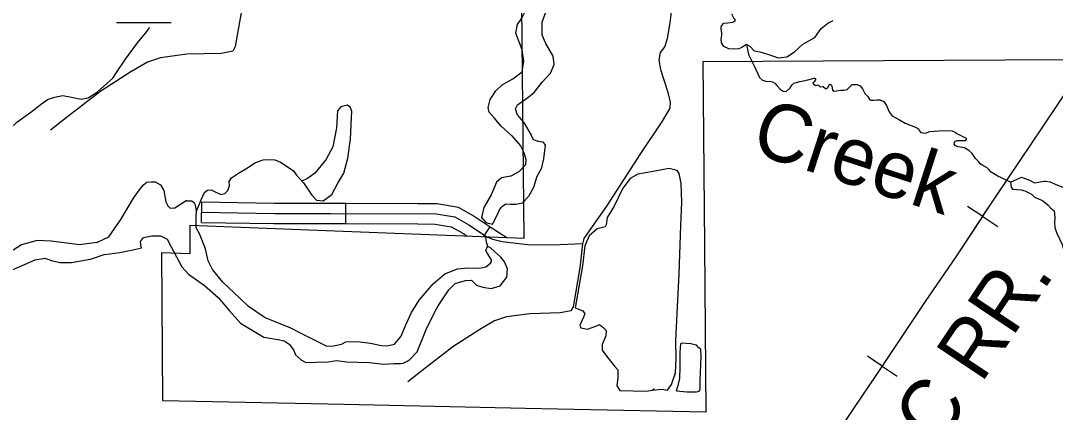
# Model space of a CAD drawing. Extents: x 22866 to 28196, y 1324810 to 1328105.
# Drawn here: x 25465.4 to 25647.4, y 1325934.5 to 1326003.4 of the extents above; entities that cross this region are included whole.
import ezdxf

# ---------------------------------------------------------------- set-up
doc = ezdxf.new("R2010")
doc.units = 0
for name, color, linetype in [('Level 34', 7, 'Continuous'), ('Level 35', 7, 'Continuous'), ('Level 40', 7, 'Continuous'), ('Level 44', 7, 'Continuous'), ('Level 45', 7, 'Continuous'), ('Level 6', 7, 'Continuous')]:
    doc.layers.add(name, color=color, linetype=linetype)

msp = doc.modelspace()

# ---------------------------------------------------------------- linework, layer by layer
at = {"layer": 'Level 34'}
for points in [[(25522.24, 1326039.09), (25522.16, 1326037.93), (25520.61, 1326035.38), (25516.36, 1326029.04), (25509.71, 1326018.67), (25506.39, 1326014.03), (25505.23, 1326012.32), (25505, 1326011.24), (25504.46, 1326006.52), (25503.14, 1325998.86), (25502.68, 1325998.05), (25500.67, 1325997.66), (25494.64, 1325997.51), (25490, 1325996.89), (25487.69, 1325996.12), (25484.77, 1325994.41), (25479.51, 1325991.01), (25473.41, 1325986.29), (25470.63, 1325984.13)], [(25583.69, 1326013.62), (25581.55, 1326010.09), (25580.3, 1326007.04), (25579.89, 1326005.38), (25579.61, 1326003.03), (25579.12, 1326000.26), (25578.71, 1325998.87), (25577.88, 1325997.83), (25577.67, 1325996.45), (25577.95, 1325994.85), (25579.19, 1325990.98), (25579.68, 1325989.06)], [(25579.68, 1325989.06), (25579.61, 1325988.03), (25578.22, 1325985.74), (25574.42, 1325980.06), (25568.47, 1325970.78), (25565.49, 1325966.63), (25564.46, 1325965.1), (25564.25, 1325964.13), (25563.76, 1325959.91), (25562.59, 1325953.05), (25562.17, 1325952.33), (25560.37, 1325951.98), (25554.98, 1325951.84), (25550.83, 1325951.29), (25548.75, 1325950.59), (25546.14, 1325949.07), (25541.44, 1325946.02), (25535.97, 1325941.8), (25533.48, 1325939.86)], [(25564.25, 1325964.13), (25558.96, 1325963.91), (25554.57, 1325963.94), (25550.07, 1325964.5), (25548.48, 1325964.91), (25547.34, 1325965.38)]]:
    msp.add_lwpolyline(points, dxfattribs=at)
at = {"layer": 'Level 35'}
for points in [[(25552.51, 1326001.24), (25552.77, 1326002.74), (25553.55, 1326003.84), (25554.02, 1326004.78), (25554.28, 1326005.82), (25554.28, 1326006.66), (25554.02, 1326007.55), (25553.19, 1326008.34), (25552.35, 1326009.38)], [(25557.11, 1326000.87), (25557.16, 1326003.16), (25557.68, 1326004.62), (25558.36, 1326005.72), (25559.77, 1326007.34), (25560.87, 1326008.44), (25560.87, 1326009.07), (25560.71, 1326009.59), (25559.93, 1326010.17), (25558.57, 1326010.32)], [(25588.74, 1326001.21), (25588.65, 1326002.04), (25588.6, 1326002.2), (25588.7, 1326002.51), (25589.12, 1326002.98), (25589.8, 1326003.04), (25590.64, 1326003.14), (25591.06, 1326003.35), (25591.06, 1326003.61), (25590.85, 1326003.87), (25590.52, 1326004.54)], [(25482.25, 1325994.27), (25483.82, 1325996.65), (25485.94, 1325999.53), (25487.32, 1326001.2), (25488.13, 1326002.22)], [(25596.86, 1325997.54), (25598.64, 1325996.86), (25600.2, 1325997.07), (25601.51, 1325997.91), (25602.97, 1325999.27), (25605.12, 1326000.47), (25606.22, 1326002.04), (25607.42, 1326002.98), (25608.36, 1326003.45)], [(25549.89, 1325984.86), (25548.69, 1325986.33), (25547.8, 1325987.32), (25547.65, 1325988.11), (25547.96, 1325989.57), (25549, 1325991.09), (25550.1, 1325992.14), (25551.98, 1325993.18), (25553.6, 1325994.39), (25553.92, 1325996.27), (25553.6, 1325998.31), (25552.51, 1326001.24)], [(25552.77, 1325986.8), (25552.45, 1325987.9), (25552.82, 1325988.58), (25554.6, 1325989.89), (25555.75, 1325990.78), (25557.16, 1325992.61), (25558.62, 1325994.18), (25559.25, 1325995.69), (25559.04, 1325997.16), (25557.79, 1325999.41), (25557.11, 1326000.87)], [(25593.72, 1325998.85), (25593.09, 1325999.22), (25592.26, 1325998.69), (25591.74, 1325998.48), (25590.9, 1325998.38), (25589.96, 1325998.43), (25589.12, 1325998.85), (25588.7, 1325999.53), (25588.65, 1326000.16), (25588.76, 1326000.84), (25588.74, 1326001.21)], [(25593.09, 1325999.22), (25593.45, 1325997.47), (25594.41, 1325995.48), (25595.38, 1325993.44), (25595.89, 1325992.92)], [(25593.72, 1325998.85), (25594.45, 1325998.12), (25595.45, 1325997.91), (25596.86, 1325997.54)], [(25460.02, 1325981.17), (25462.22, 1325983.23), (25464.68, 1325985.53), (25467.19, 1325987.31), (25469.07, 1325988.78), (25470.12, 1325989.56), (25471.32, 1325989.98), (25472.78, 1325990.24), (25474.3, 1325989.93), (25476.02, 1325989.62), (25477.28, 1325989.82), (25478.9, 1325990.87), (25481.62, 1325993.28), (25482.25, 1325994.27)], [(25595.89, 1325992.92), (25596.49, 1325992.79), (25596.81, 1325992.71), (25597.2, 1325992.74), (25597.67, 1325992.66), (25598.09, 1325992.4), (25598.4, 1325992.01), (25599.03, 1325991.38), (25599.53, 1325990.99), (25600.07, 1325990.96), (25600.78, 1325991.59), (25601.12, 1325992.14), (25601.43, 1325992.4), (25602.53, 1325992.71), (25603.87, 1325993.03), (25604.99, 1325993.29)], [(25606.06, 1325991.8), (25605.75, 1325992.06), (25605.43, 1325991.98), (25605.23, 1325991.96), (25604.89, 1325992.24), (25604.83, 1325992.56), (25605.12, 1325992.79), (25605.28, 1325992.98), (25605.28, 1325993.19), (25604.99, 1325993.29)], [(25606.06, 1325991.8), (25606.56, 1325991.82), (25607.06, 1325991.42), (25607.4, 1325991.63), (25607.71, 1325992.18), (25607.84, 1325992.24), (25607.89, 1325992.21), (25608.08, 1325991.97), (25608.23, 1325991.21), (25608.52, 1325991.01), (25608.94, 1325991.08), (25609.7, 1325991.16), (25610.2, 1325991.21), (25610.8, 1325991.32), (25611.35, 1325991.84), (25611.69, 1325992.16), (25612.16, 1325992.21), (25612.57, 1325992.16), (25613.1, 1325991.97), (25613.49, 1325991.42), (25613.88, 1325990.61), (25614.4, 1325990.12), (25614.77, 1325989.46), (25614.95, 1325989.41), (25615.53, 1325989.41), (25616, 1325989.51), (25616.57, 1325989.49), (25617.23, 1325989.2), (25617.7, 1325988.49), (25618.2, 1325987.37), (25618.74, 1325986.69), (25620.03, 1325985.95), (25620.99, 1325985.35), (25622.8, 1325984.67)], [(25513.92, 1325976.24), (25515.12, 1325974.88), (25516.63, 1325972.68), (25517.42, 1325971.84), (25518.62, 1325971.68), (25520.14, 1325972.84), (25521.18, 1325974.82), (25522.23, 1325976.55), (25522.91, 1325979.22), (25523.43, 1325982.57), (25523.59, 1325986.39), (25523.64, 1325987.44), (25523.38, 1325988.12), (25522.86, 1325988.54), (25521.7, 1325988.28), (25521.13, 1325987.54), (25520.92, 1325984.56), (25520.29, 1325981.21), (25519.04, 1325978.91), (25517.16, 1325976.55), (25515.85, 1325975.61), (25514.85, 1325975.14)], [(25552.77, 1325986.8), (25553.97, 1325985.39), (25555.17, 1325983.24)], [(25549.89, 1325984.86), (25551.78, 1325983.14), (25553.29, 1325981.36), (25553.92, 1325980.21), (25554.28, 1325979), (25554.18, 1325978.06), (25553.03, 1325976.8), (25551.62, 1325976.02), (25549.95, 1325975.76)], [(25622.8, 1325984.67), (25623.37, 1325984.37), (25623.47, 1325984.1), (25623.76, 1325983.71), (25624.57, 1325983.61), (25625.36, 1325983.9), (25626.12, 1325983.97), (25626.93, 1325984.05), (25628, 1325984.1), (25629.28, 1325984.03), (25629.78, 1325983.79), (25630.16, 1325983.51)], [(25555.17, 1325983.24), (25555.54, 1325982.51), (25556.43, 1325982.19), (25557.26, 1325982.09), (25557.68, 1325981.51), (25557.37, 1325979.11), (25556.95, 1325977.33), (25556.22, 1325975.97), (25555.59, 1325974.08), (25554.7, 1325972.46), (25553.6, 1325971.31), (25552.56, 1325971.05), (25551.57, 1325971.05), (25550.73, 1325971.15), (25550, 1325970.58)], [(25639.53, 1325974.97), (25637.93, 1325975.76), (25637.28, 1325976.04), (25636.15, 1325976.78), (25635.74, 1325977.22), (25635.45, 1325977.51), (25634.66, 1325977.95), (25634.22, 1325978.24), (25633.93, 1325978.61), (25633.38, 1325979.16), (25632.78, 1325980.02), (25632.21, 1325980.57), (25631.45, 1325981.02), (25630.3, 1325981.2), (25629.83, 1325981.38), (25629.64, 1325981.7), (25629.67, 1325981.98), (25629.88, 1325982.22), (25630.12, 1325982.32), (25630.85, 1325982.32), (25631.4, 1325982.3), (25631.68, 1325982.32), (25631.81, 1325982.53), (25631.81, 1325982.69), (25630.16, 1325983.51)], [(25496.33, 1325969.89), (25497.4, 1325972.57), (25497.77, 1325973.25), (25498.24, 1325973.57), (25498.92, 1325973.62), (25499.6, 1325973.31), (25500.59, 1325972.84), (25501.27, 1325972.99), (25501.85, 1325973.52), (25502.11, 1325974.41), (25502.05, 1325975.09), (25502.47, 1325975.77), (25503.68, 1325976.6), (25505.3, 1325977.49), (25506.55, 1325978.38), (25508.07, 1325978.91), (25509.11, 1325978.96), (25510.11, 1325978.91), (25511.1, 1325978.54), (25513.3, 1325977.02), (25513.92, 1325976.24)], [(25580.7, 1325943.95), (25580.67, 1325947.2), (25581.22, 1325958.84), (25581.5, 1325967.35), (25581.71, 1325971.48), (25581.57, 1325974.74), (25581.22, 1325976.54), (25580.87, 1325977.02), (25579.49, 1325977.37), (25576.65, 1325976.88), (25573.96, 1325976.4), (25572.64, 1325975.64), (25571.33, 1325973.91), (25569.8, 1325970.79), (25568.56, 1325968.78), (25568.42, 1325967.47), (25568.21, 1325967.12), (25566.83, 1325966.77), (25565.38, 1325965.53), (25564.61, 1325963.79), (25564.2, 1325960.26), (25562.95, 1325952.85), (25563.23, 1325952.74), (25564.27, 1325952.33), (25564.61, 1325951.84), (25564.41, 1325951.22), (25563.78, 1325949.83), (25563.92, 1325949.35), (25565.1, 1325949.14), (25566.55, 1325949.63), (25567.24, 1325949.97), (25567.8, 1325949.49), (25568.42, 1325948.86), (25568.35, 1325947.96), (25567.66, 1325946.44), (25567.66, 1325945.4), (25568.49, 1325944.29), (25569.87, 1325942.63), (25570.43, 1325941.94), (25570.43, 1325940.62), (25570.29, 1325939.17), (25570.77, 1325938.34), (25570.84, 1325938.33)], [(25478.78, 1325964.39), (25480.86, 1325965.39), (25483, 1325968.43), (25485.2, 1325972.19), (25486.29, 1325973.66), (25486.97, 1325974.55), (25487.6, 1325975.02), (25488.38, 1325975.07), (25489.06, 1325975.07), (25490, 1325974.5), (25490.58, 1325973.5), (25490.89, 1325971.51), (25491.26, 1325970.83), (25491.68, 1325970.42), (25492.51, 1325970.47), (25494.5, 1325971.78)], [(25549.95, 1325975.76), (25549.11, 1325975.02), (25548.17, 1325972.77), (25546.89, 1325970.54)], [(25639.53, 1325974.97), (25641.49, 1325975.9)], [(25639.53, 1325974.97), (25639.63, 1325974.12), (25639.89, 1325973.75), (25640.62, 1325973.73), (25641.41, 1325973.65), (25642.06, 1325973.46), (25643.21, 1325972.86), (25643.76, 1325972.34), (25645.15, 1325971.79), (25646.09, 1325971.03), (25646.64, 1325970.43), (25647.21, 1325969.93), (25647.29, 1325969.43), (25647.32, 1325968.65), (25647.29, 1325967.97), (25647.32, 1325967.03), (25647.63, 1325966.11), (25648.15, 1325965.04), (25648.6, 1325964.04), (25648.86, 1325963.22), (25649.2, 1325962.13)], [(25641.49, 1325975.9), (25642.87, 1325975.32), (25643.76, 1325974.88), (25645.43, 1325975.14), (25645.72, 1325975.16), (25646.51, 1325975.06), (25647.53, 1325974.56), (25648.73, 1325974.09), (25650.06, 1325973.46), (25651.68, 1325972.71), (25652.49, 1325972.08), (25654.14, 1325970.95)], [(25496.33, 1325969.89), (25496.15, 1325970.95), (25495.94, 1325971.32), (25495.52, 1325971.63), (25494.68, 1325971.63), (25494.5, 1325971.78)], [(25508.2, 1325951.21), (25505.48, 1325953.1), (25504.01, 1325954.51), (25500.93, 1325957.39), (25499.15, 1325959.64), (25498.37, 1325961.15), (25497.9, 1325963.25), (25496.91, 1325965.76), (25496.28, 1325966.96), (25496.23, 1325968.11), (25496.23, 1325969.11), (25496.33, 1325969.89)], [(25546.89, 1325970.54), (25546.43, 1325968.78), (25547.23, 1325967.88)], [(25547.23, 1325967.88), (25548.42, 1325967.63), (25549.28, 1325969.3)], [(25549.28, 1325969.3), (25549.58, 1325969.99), (25550, 1325970.58)], [(25547.21, 1325967.9), (25547.15, 1325967.73)], [(25480.16, 1325962.25), (25482.84, 1325962.62), (25485.09, 1325963.09), (25486.19, 1325963.3), (25486.61, 1325963.46), (25486.5, 1325963.98), (25486.45, 1325964.56), (25486.97, 1325965.24), (25488.44, 1325965.55), (25490, 1325965.55), (25491.15, 1325964.97), (25491.83, 1325963.61), (25493.72, 1325960.11), (25494.92, 1325958.8), (25497.74, 1325956.81), (25500.15, 1325954.72), (25502.13, 1325952.36), (25504.07, 1325950.17), (25508.14, 1325947.71)], [(25478.78, 1325964.39), (25475.72, 1325963.98), (25470.75, 1325964.6), (25468.3, 1325964.71), (25465.52, 1325963.98), (25461.71, 1325961.57), (25458.62, 1325958.64), (25455.85, 1325955.34), (25452.82, 1325952.46), (25450.36, 1325950.89), (25447.28, 1325949.27), (25442.83, 1325947.02), (25441.31, 1325946.81), (25440.63, 1325946.91), (25440.43, 1325947.91), (25440.63, 1325949.53)], [(25547.19, 1325965.38), (25547.27, 1325964.49), (25547.51, 1325963.68)], [(25480.16, 1325962.25), (25477.6, 1325961.4), (25474.31, 1325960.77), (25472.27, 1325960.77), (25471.02, 1325961.09), (25469.71, 1325961.56), (25467.88, 1325961.24), (25463.69, 1325959.46), (25461.18, 1325957.21), (25460.4, 1325956.17), (25459.98, 1325955.54), (25458.36, 1325954.18), (25456.32, 1325951.87), (25454.02, 1325949.78), (25451.09, 1325947.37), (25447.17, 1325945.59), (25443.72, 1325944.76), (25441.31, 1325943.92), (25439.22, 1325942.61), (25435.72, 1325940.99), (25432.69, 1325938.69), (25430.19, 1325936.53)], [(25538.85, 1325953.22), (25540.69, 1325956.04), (25541.84, 1325957.14), (25543.62, 1325957.71), (25544.67, 1325957.76), (25545.55, 1325956.87), (25546.7, 1325956.51), (25548.17, 1325956.25), (25549.74, 1325956.77), (25550.94, 1325958.29), (25551.04, 1325959.75), (25550.52, 1325960.96), (25549.84, 1325961.79), (25548.8, 1325962.73), (25547.96, 1325963.52)], [(25548.22, 1325961.32), (25547.49, 1325962.42), (25547.23, 1325962.94), (25547.51, 1325963.68)], [(25547.96, 1325963.52), (25547.51, 1325963.68)], [(25535.48, 1325954.25), (25537.97, 1325957.08), (25540.01, 1325958.86), (25542.26, 1325959.75), (25544.04, 1325959.91), (25546.18, 1325959.86), (25547.23, 1325960.12), (25548.06, 1325960.75), (25548.22, 1325961.06), (25548.22, 1325961.32)], [(25534.17, 1325952.06), (25535.48, 1325954.25)], [(25536.73, 1325949.08), (25538.39, 1325952.43), (25538.85, 1325953.22)], [(25508.2, 1325951.21), (25512.85, 1325949.38), (25514.89, 1325948.28), (25517.71, 1325946.92)], [(25517.71, 1325946.92), (25519.22, 1325946.15), (25520.42, 1325946.2), (25521.83, 1325946.51), (25522.56, 1325946.88), (25524.65, 1325946.98), (25526.95, 1325946.67), (25528.78, 1325946.25), (25529.78, 1325946.2), (25531.14, 1325946.51), (25532.34, 1325947.87), (25533.17, 1325949.86), (25534.17, 1325952.06)], [(25508.14, 1325947.71), (25510.64, 1325947.3), (25511.74, 1325947.09), (25512.63, 1325946.51), (25513.36, 1325945.47), (25513.73, 1325944.58), (25514.77, 1325943.64), (25515.56, 1325943.27), (25517.44, 1325943.32)], [(25517.44, 1325943.32), (25519.48, 1325943.37), (25520.94, 1325943.58), (25522.77, 1325943.37), (25524.65, 1325943.32), (25526.74, 1325943.27), (25529.2, 1325942.96), (25531.08, 1325943.06), (25532.23, 1325943.06), (25532.7, 1325943.11), (25533.75, 1325943.69), (25535.11, 1325945.15), (25536.73, 1325949.08)], [(25580.75, 1325938.25), (25582.59, 1325938.11), (25583.8, 1325938.08), (25584.28, 1325938.08), (25584.73, 1325938.22), (25584.91, 1325938.6), (25584.94, 1325940.09), (25585.11, 1325944.34), (25585.04, 1325945.63), (25584.7, 1325945.83), (25584.28, 1325946.32), (25583.31, 1325946.56), (25581.72, 1325946.66), (25581.45, 1325946.53), (25581.38, 1325945.04), (25581.38, 1325942.44), (25581.31, 1325940.43), (25581.03, 1325939.22), (25580.72, 1325938.22)], [(25576.85, 1325938.61), (25576.52, 1325938.41), (25578.18, 1325938.54), (25579.21, 1325938.41), (25579.91, 1325939.38), (25580.6, 1325941.45), (25580.7, 1325943.95)], [(25570.84, 1325938.33), (25575.41, 1325938.2), (25576.52, 1325938.41)]]:
    msp.add_lwpolyline(points, dxfattribs=at)
at = {"layer": 'Level 40'}
for p, q in [((25634.64, 1325968.94), (25631.99, 1325970.69)), ((25634.64, 1325968.94), (25637.28, 1325967.19)), ((25616.98, 1325942.63), (25614.35, 1325944.39)), ((25616.98, 1325942.63), (25619.61, 1325940.87))]:
    msp.add_line(p, q, dxfattribs=at)
for points in [[(25634.63, 1325968.94), (25639.05, 1325975.56), (25645.24, 1325984.75), (25653.04, 1325996.34)], [(25634.63, 1325968.94), (25639.05, 1325975.56), (25645.24, 1325984.75), (25653.04, 1325996.34)], [(25492.71, 1325755.52), (25496.31, 1325761.34), (25500.34, 1325767.54), (25504.76, 1325774.59), (25516.78, 1325792.11), (25526.44, 1325807.02), (25536.83, 1325822.38), (25545.04, 1325834.64), (25558.16, 1325854.38), (25568.88, 1325870.46), (25579.1, 1325885.61), (25587.97, 1325899.18), (25600.25, 1325917.68), (25612.11, 1325935.34), (25615.88, 1325940.99), (25624.6, 1325954.01), (25629.96, 1325961.87), (25634.64, 1325968.94)]]:
    msp.add_lwpolyline(points, dxfattribs=at)
at = {"layer": 'Level 44'}
msp.add_line((25482.24, 1326003.07), (25491.84, 1326003.07), dxfattribs=at)
at = {"layer": 'Level 45'}
for p, q in [((25497.22, 1325967.91), (25497.28, 1325971.51)), ((25522.59, 1325967.69), (25522.6, 1325971.29)), ((25546.81, 1325965.4), (25547.98, 1325967.16))]:
    msp.add_line(p, q, dxfattribs=at)
for points in [[(25624.6, 1325954.01), (25629.96, 1325961.87), (25635.14, 1325969.7), (25639.05, 1325975.56), (25645.24, 1325984.75), (25656.03, 1326000.79), (25663.49, 1326012.3), (25670.2, 1326022.41), (25674.43, 1326028.62)], [(25497.28, 1325971.51), (25509.95, 1325971.3)], [(25509.95, 1325971.3), (25510.06, 1325971.3), (25519.95, 1325971.3), (25522.6, 1325971.29)], [(25522.6, 1325971.29), (25535.27, 1325971.24)], [(25535.27, 1325971.24), (25538.64, 1325971.23), (25542.34, 1325970.6), (25545.16, 1325969.03), (25547.98, 1325967.16)], [(25497.25, 1325969.71), (25510.05, 1325969.5), (25519.94, 1325969.5), (25538.49, 1325969.43), (25541.74, 1325968.88), (25544.23, 1325967.49), (25547.54, 1325965.29)], [(25497.22, 1325967.91), (25509.89, 1325967.7)], [(25509.89, 1325967.7), (25510.03, 1325967.7), (25519.94, 1325967.7), (25522.59, 1325967.69)], [(25522.59, 1325967.69), (25535.26, 1325967.64)], [(25535.26, 1325967.64), (25538.33, 1325967.63), (25541.13, 1325967.15), (25543.29, 1325965.95), (25543.96, 1325965.51)], [(25547.98, 1325967.16), (25550.89, 1325965.24)], [(25587.97, 1325899.18), (25600.25, 1325917.68), (25612.11, 1325935.34), (25615.88, 1325940.99), (25624.6, 1325954.01)]]:
    msp.add_lwpolyline(points, dxfattribs=at)
at = {"layer": 'Level 6'}
msp.add_lwpolyline([(25649.32, 1325996.51), (25617.16, 1325996.35), (25585.42, 1325996.19), (25585.69, 1325963.85), (25585.93, 1325934.49), (25559.89, 1325935.04), (25554.2, 1325935.17), (25522.31, 1325935.85), (25490.39, 1325936.53), (25490.24, 1325962.61), (25495.22, 1325962.44), (25495.22, 1325967.45), (25522.1, 1325966.38), (25553.99, 1325965.11), (25553.63, 1325999.84), (25553.3, 1326032.12), (25585.16, 1326028.45), (25586.05, 1326062.39), (25616.74, 1326060.69), (25617.51, 1326093.33), (25649.2, 1326092.61)], dxfattribs=at)

# ---------------------------------------------------------------- texts
at = {"layer": 'Level 35'}
msp.add_text('Creek', height=10.139, rotation=342.0645, dxfattribs=at).set_placement((25593.51, 1325980.32))
at = {"layer": 'Level 40'}
msp.add_text('PACIFIC RR.', height=10.1394, rotation=56.2185, dxfattribs=at).set_placement((25602.56, 1325891.84))

doc.saveas('drawing.dxf')
